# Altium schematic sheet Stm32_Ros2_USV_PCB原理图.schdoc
size 297 x 209 mm; Symbol: Drawing-Symbol_A4; Company: GDOU_TH; Drawed: SU; Version: V1.0; Page Size: A4; @Project Name: Stm32_Ros2_USV; @Update Date: 2026-01-12; @Create Date: 2026-01-12; Device: Drawing-Symbol_A4; @Board Name: Board1; @Page Name: P1; @Create Time: 16:35:37; @Page Count: 1; @Page No: 1; @Schematic Name: Schematic1; @Update Time: 16:35:37; @Assembly Variant: Basic; Border: 1; Title Block Position: 3; Size: A4; Width: 1170; Height: 825; Region Start: 1; X Region Count: 6; Y Region Count: 4; Blade Width: 10; Title Block: 1
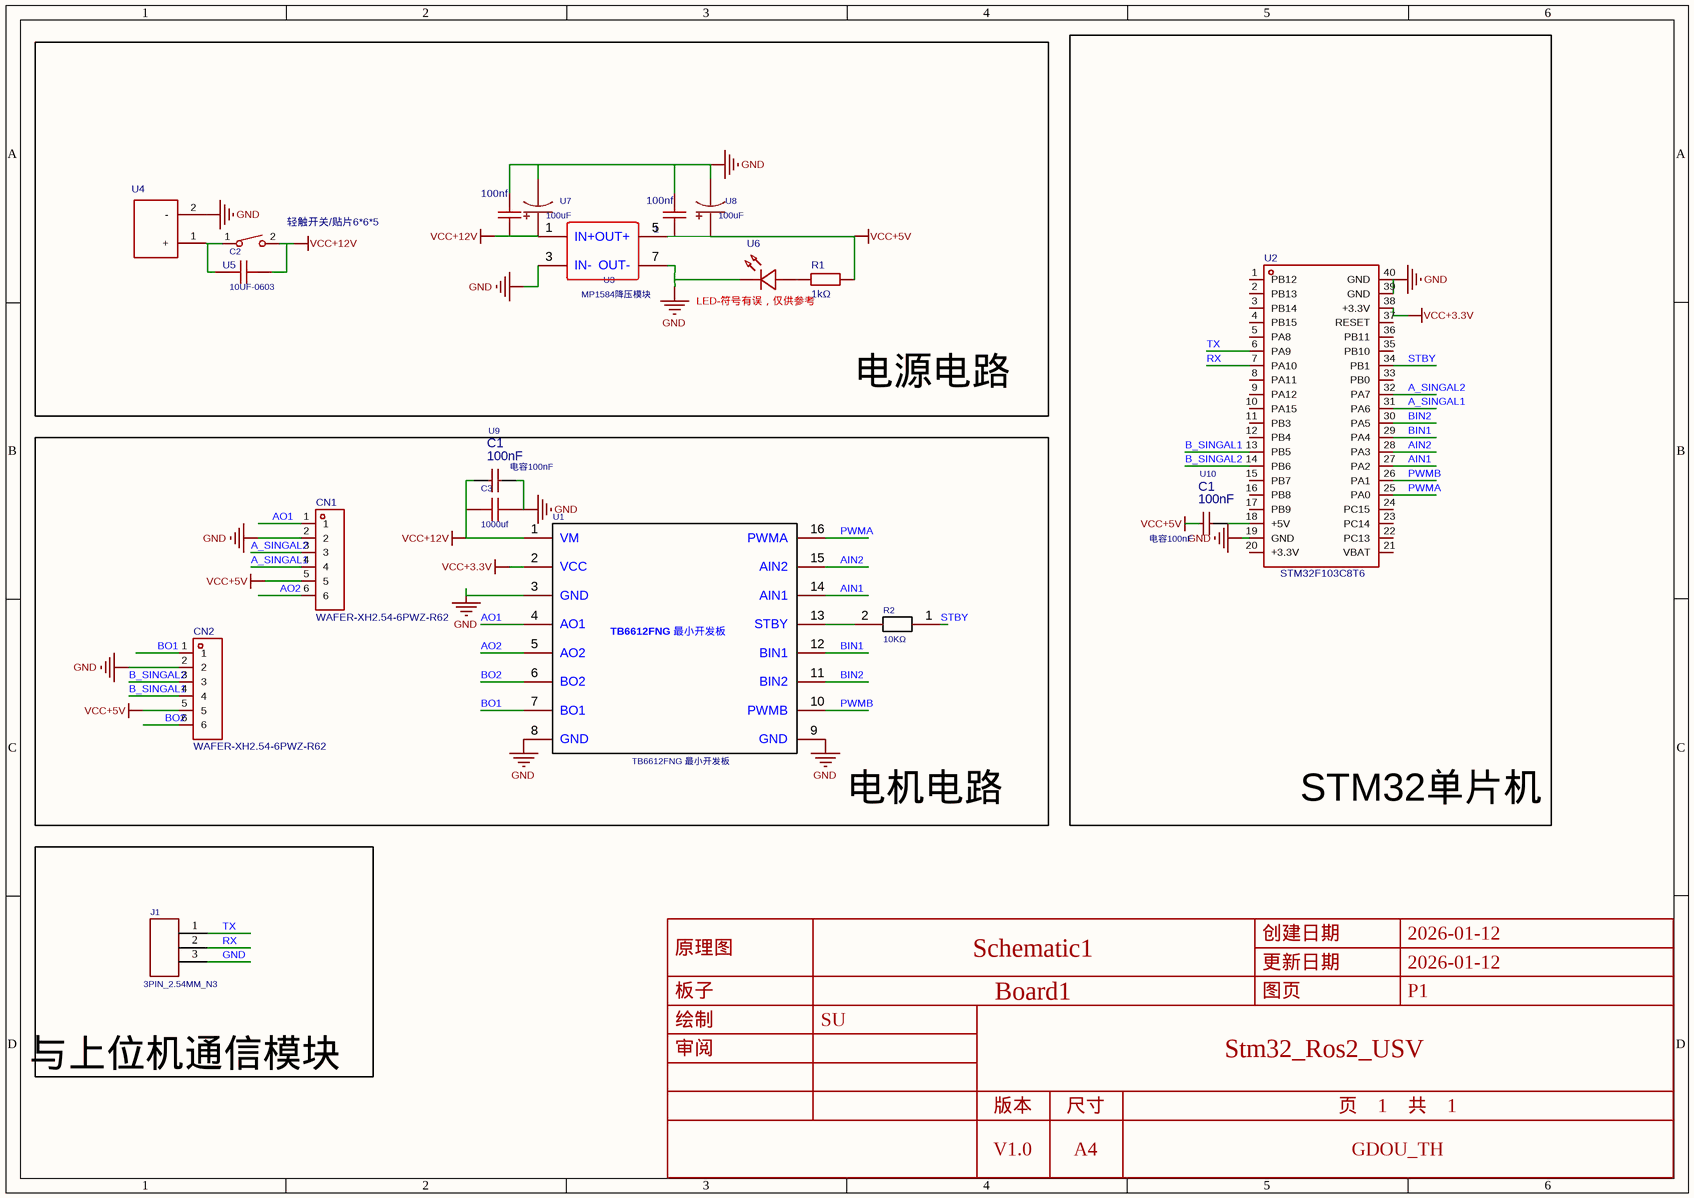
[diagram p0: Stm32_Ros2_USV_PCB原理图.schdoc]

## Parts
1  100nf  [C0603_7]
104  100nf  [C0603_7]
C2  10UF-0603  [10UF-C0603]
C3  1000uf  [电解电容1000UF/10V Φ3.5MM]
CN1  WAFER-XH2.54-6PWZ-R62  [CONN-TH_6P-P2.50_WAFER-XH2.54-6PWZ-R62]
CN2  WAFER-XH2.54-6PWZ-R62  [CONN-TH_6P-P2.50_WAFER-XH2.54-6PWZ-R62]
J1  3PIN_2.54MM_N3  [3PIN]
R1  1kΩ  [R0805]
R2  10KΩ  [电阻10KK COPY]
U1  TB6612FNG 最小开发板  [TB6612FNG封装]
U2  STM32F103C8T6  [CONN-TH_L53.3-W22.9_STM32F103C8T6-CARD]
U3  MP1584降压模块  [MP1584降压模块]
U4  (no value)  [接线端子]
U5  轻触开关/贴片6*6*5  [SW-SMD_L6.0-W5.9-LS6.6]
U6  LED-符号有误，仅供参考  [LED-TH_BD3.0-P2.54-FD]
U7  100uF  [100UF电解电容]
U8  100uF  [100UF电解电容]
U9  电容100nF  [电容100NF ±10% 16V]
U10  电容100nF  [电容100NF ±10% 16V]

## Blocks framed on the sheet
电源电路: 1 104 C2 R1 U3-U8
STM32单片机: U2 U10
电机电路: C3 CN1 CN2 R2 U1 U9

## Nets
GND: 1.2 104.2 C3.2 CN1.2 CN2.2 J1.3 U1.3(GND) U1.8(GND) U1.9(GND) U2.19(GND) U2.39(GND) U2.40(GND) U3.3(IN-) U3.7(OUT-) U4.2(-) U6.2(K) U7.2 U8.2 U9.2
VCC+3.3V: U1.2(VCC) U2.38(+3.3V)
VCC+5V: 1.1 CN1.5 CN2.5 R1.2 U3.5(OUT+) U8.1 U10.1
VCC+12V: 104.1 C2.2 C3.1 U1.1(VM) U3.1(IN+) U5.2 U7.1 U9.1
A_SINGAL1: CN1.4 U2.31(PA6)
A_SINGAL2: CN1.3 U2.32(PA7)
AIN1: U1.14(AIN1) U2.27(PA2)
AIN2: U1.15(AIN2) U2.28(PA3)
AO1: CN1.1 U1.4(AO1)
AO2: CN1.6 U1.5(AO2)
B_SINGAL1: CN2.4 U2.13(PB5)
B_SINGAL2: CN2.3 U2.14(PB6)
BIN1: U1.12(BIN1) U2.29(PA4)
BIN2: U1.11(BIN2) U2.30(PA5)
BO1: CN2.1 U1.7(BO1)
BO2: CN2.6 U1.6(BO2)
PWMA: U1.16(PWMA) U2.25(PA0)
PWMB: U1.10(PWMB) U2.26(PA1)
RX: J1.2 U2.7(PA10)
STBY: R2.1 U2.34(PB1)
TX: J1.1 U2.6(PA9)
NetC2_1: C2.1 U4.1(+) U5.1
NetR1_1: R1.1 U6.1(A)
NetR2_2: R2.2 U1.13(STBY)
NetU2_18: U2.18(+5V) U10.2

Not connected (* = marked no-connect by the designer): U2 1(PB12) 2(PB13) 3(PB14) 4(PB15) 5(PA8) 8(PA11) 9(PA12) 10(PA15) 11(PB3) 12(PB4) 15(PB7) 16(PB8) 17(PB9) 20(+3.3V) 21(VBAT) 22(PC13) 23(PC14) 24(PC15) 33(PB0) 35(PB10) 36(PB11) 37(RESET)

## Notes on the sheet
- 与上位机通信模块

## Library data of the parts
1 104 = 100pF: 温度系数:C0G;精度:±5%;额定电压:50V;容值:100pF;; Manufacturer: SAMSUNG(三星); ManufacturerPart: CL10C101JB8NNNC; AddInBom: yes; ModelId: ac125912035d415993ca9572d50418b1f91408f7b3e044a3b98f2ee2de657ebb; ModelName: C0603_L1.6-W0.8-H0.8; ModelTransform: 62.992,31.496,0,0,0,0,0,0,0; Temperature Coefficient: C0G; Tolerance: ±5%; Voltage Rated: 50V; Value: 100pF
C2 = 10UF-0603: Manufacturer: Samsung Electro-Mechanics; Value: 10uF
C3 = 1000u
CN1 CN2 = WAFER-XH2.54-6PWZ-R62: 插针结构:1x6P;间距:2.5mm;安装方式:弯插;参考系列:XH;总PIN数:6P;排数:1;每排PIN数:6;行距:-;额定电流:3A;触头材质:铜合金;触头镀层:锡;工作温度:-25℃~+85℃;; Manufacturer: XUNPU(讯普); AddInBom: yes; ModelId: 4bb878ffa3f24570bdbe829d9b9969a10819f05c4eef4c71ace90d822a990e87; ModelTransform: 689.36866,294.881,0,0,0,0,-0.005,-133.858,-137.795; Pins Structure: 1x6P; Pitch: 2.5mm; Reference Series: XH; Number of PINs Per Row: 6; Current Rating: 3A; Voltage Rating: 250V; Plastic Material: PA66; Flame Retardant Rating: UL94V-2; Z-Height of the Board: 5.75mm; X-Length of Bottom Edge on Board (Spacing Line): 17.5mm; Y-Width of Bottom Edge on Board: 7.17mm
R1 = 0805-1k欧: 电阻类型:厚膜电阻;阻值:1kΩ;精度:±1%;功率:125mW;最大工作电压:150V;温度系数:±100ppm/℃;; Manufacturer: UNI-ROYAL(厚声); ManufacturerPart: 0805W8F1001T5E; AddInBom: yes; ModelId: 37a81e68749a4138bd2dfa6897b24b850c919678dc41425ab7ee2f719f390d97; ModelName: R0805_L2.0-W1.3-H0.6; ModelTransform: 78.74,51.181,0,0,0,0,0,-0.0005,0; Tolerance: ±1%; Power(Watts): 125mW; Overload Voltage (Max): 150V
U2 = LCKFB-DKX-STM32F103C8T6: 搭载Contex M3内核,程序存储容量64KB,RAM总容量20KB,最高72MHz主频,提供高效的计算能力和稳定的运行环境。; Manufacturer: 立创开发板; AddInBom: yes
U4 = 接线端子: AddInBom: yes
U5 = 轻触开关/软触开关(无声)/贴片6*6*5_C9900014294: AddInBom: yes; ModelId: 32c202309ab949db9989306602160a760819f05c4eef4c71ace90d822a990e87; ModelTransform: 259.842,236.22,0,0,0,0,0,0,0
U6 = 3mmFIR: AddInBom: yes; ModelId: a497c992633541038a38947cdc58012f0819f05c4eef4c71ace90d822a990e87; ModelName: LED-TH-3mm_R; ModelTransform: 141.274,153.327,0,0,0,0,-5.984,0,-137.795
U7 U8 = 100uF: Manufacturer: TDK; ManufacturerPart: B41866C5477M000
U9 U10 = 电容100nF ±10% 16V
